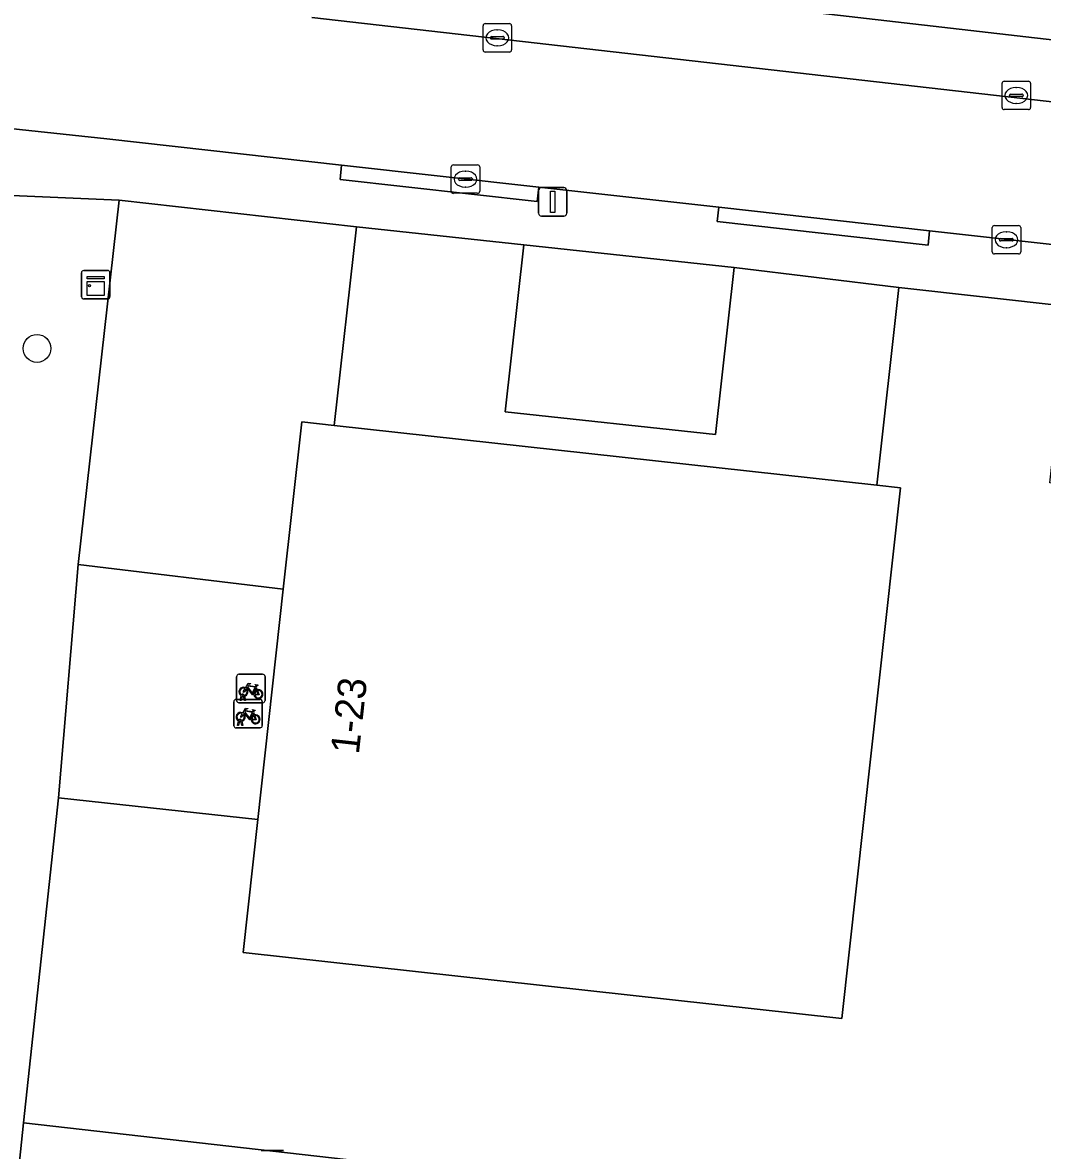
# Model space of a CAD drawing. Extents: x 161928 to 163071, y 386474 to 387428.
# Drawn here: x 162199.13 to 162234.98, y 387005.98 to 387045.64 of the extents above; entities that cross this region are included whole.
import ezdxf

# ---------------------------------------------------------------- set-up
doc = ezdxf.new("R2010")
doc.units = 0
for name, color, linetype in [('IMGEO_Boom', 7, 'Continuous'), ('IMGEO_Fietsenrek', 7, 'Continuous'), ('IMGEO_Groenvoorziening', 7, 'Continuous'), ('IMGEO_Kast', 7, 'Continuous'), ('IMGEO_Kolk', 7, 'Continuous'), ('IMGEO_Lichtmast', 7, 'Continuous'), ('IMGEO_Pand', 7, 'Continuous'), ('IMGEO_Pand_nummerreeks', 7, 'Continuous'), ('IMGEO_Parkeervlak_open', 7, 'Continuous'), ('IMGEO_Rijbaan_lokaal_open', 7, 'Continuous'), ('IMGEO_Voetpad_open', 7, 'Continuous')]:
    doc.layers.add(name, color=color, linetype=linetype)

msp = doc.modelspace()

# ---------------------------------------------------------------- linework, layer by layer
at = {"layer": 'IMGEO_Boom'}
msp.add_circle((162199.641, 387034.177), 0.489, dxfattribs=at)
at = {"layer": 'IMGEO_Fietsenrek'}
for p, q in [((162206.656, 387021.794), (162206.656, 387022.635)), ((162206.656, 387022.635), (162206.656, 387021.794)), ((162206.731, 387022.719), (162207.572, 387022.719)), ((162207.572, 387022.719), (162206.731, 387022.719)), ((162207.656, 387022.644), (162207.656, 387021.803)), ((162207.656, 387021.803), (162207.656, 387022.644)), ((162207.343, 387022.268), (162207.379, 387022.173)), ((162206.558, 387020.91), (162206.558, 387021.751)), ((162206.558, 387021.751), (162206.558, 387020.91)), ((162206.633, 387021.835), (162207.474, 387021.835)), ((162207.474, 387021.835), (162206.633, 387021.835)), ((162207.581, 387021.719), (162206.74, 387021.719)), ((162206.74, 387021.719), (162207.581, 387021.719)), ((162206.783, 387021.803), (162206.822, 387021.963)), ((162206.817, 387021.803), (162206.783, 387021.803)), ((162206.852, 387021.951), (162206.817, 387021.803)), ((162206.894, 387021.975), (162206.893, 387021.979)), ((162206.935, 387021.803), (162206.901, 387021.945)), ((162206.925, 387021.986), (162206.926, 387021.979)), ((162206.933, 387021.949), (162206.968, 387021.803)), ((162206.968, 387021.803), (162206.935, 387021.803)), ((162207.558, 387021.76), (162207.558, 387020.919)), ((162207.558, 387020.919), (162207.558, 387021.76)), ((162207.245, 387021.384), (162207.281, 387021.289)), ((162206.685, 387020.919), (162206.724, 387021.079)), ((162206.719, 387020.919), (162206.685, 387020.919)), ((162206.754, 387021.067), (162206.719, 387020.919)), ((162206.796, 387021.091), (162206.795, 387021.095)), ((162206.837, 387020.919), (162206.803, 387021.061)), ((162206.827, 387021.102), (162206.828, 387021.095)), ((162206.835, 387021.065), (162206.87, 387020.919)), ((162206.87, 387020.919), (162206.837, 387020.919)), ((162207.483, 387020.835), (162206.642, 387020.835)), ((162206.642, 387020.835), (162207.483, 387020.835))]:
    msp.add_line(p, q, dxfattribs=at)
for points in [[(162206.99, 387022.193), (162206.938, 387022.103), (162206.898, 387022.078), (162206.899, 387022.125), (162206.954, 387022.219)], [(162206.969, 387022.245), (162207.064, 387022.409), (162207.15, 387022.395), (162207.152, 387022.386), (162207.096, 387022.375), (162207.069, 387022.33), (162207.325, 387022.289)], [(162207.265, 387022.001), (162207.215, 387022.001), (162207.024, 387022.252), (162207.005, 387022.22)], [(162207.312, 387022.264), (162207.055, 387022.305), (162207.038, 387022.276), (162207.205, 387022.056), (162207.312, 387022.264)], [(162207.36, 387022.166), (162207.33, 387022.243), (162207.221, 387022.025), (162207.264, 387022.025)], [(162207.294, 387022.025), (162207.414, 387022.024), (162207.37, 387022.138)], [(162207.39, 387022.145), (162207.445, 387022), (162207.295, 387022)], [(162207.325, 387022.289), (162207.35, 387022.338), (162207.344, 387022.342), (162207.321, 387022.346), (162207.309, 387022.353), (162207.308, 387022.356), (162207.31, 387022.361), (162207.405, 387022.346), (162207.407, 387022.336), (162207.397, 387022.323), (162207.385, 387022.317), (162207.371, 387022.323), (162207.343, 387022.268)], [(162206.892, 387021.309), (162206.84, 387021.219), (162206.8, 387021.194), (162206.801, 387021.241), (162206.856, 387021.335)], [(162206.871, 387021.361), (162206.966, 387021.525), (162207.052, 387021.511), (162207.054, 387021.502), (162206.998, 387021.491), (162206.971, 387021.446), (162207.227, 387021.405)], [(162207.167, 387021.117), (162207.117, 387021.117), (162206.926, 387021.368), (162206.907, 387021.336)], [(162207.214, 387021.38), (162206.957, 387021.421), (162206.94, 387021.392), (162207.107, 387021.172), (162207.214, 387021.38)], [(162207.262, 387021.282), (162207.232, 387021.359), (162207.123, 387021.141), (162207.166, 387021.141)], [(162207.196, 387021.141), (162207.316, 387021.14), (162207.272, 387021.254)], [(162207.292, 387021.261), (162207.347, 387021.116), (162207.197, 387021.116)], [(162207.227, 387021.405), (162207.252, 387021.454), (162207.246, 387021.458), (162207.223, 387021.462), (162207.211, 387021.469), (162207.21, 387021.472), (162207.212, 387021.477), (162207.307, 387021.462), (162207.309, 387021.452), (162207.299, 387021.439), (162207.287, 387021.433), (162207.273, 387021.439), (162207.245, 387021.384)]]:
    msp.add_lwpolyline(points, dxfattribs=at)
for centre, radius, start, end in [((162206.734, 387022.641), 0.0779, 92.4484, 184.2845), ((162206.734, 387022.641), 0.0779, 92.4484, 184.2845), ((162207.578, 387022.641), 0.0779, 2.4484, 94.2845), ((162207.578, 387022.641), 0.0779, 2.4484, 94.2845), ((162206.896, 387022.104), 0.159, 62.6766, 242.1369), ((162206.896, 387022.104), 0.129, 63.3192, 238.903), ((162206.896, 387022.104), 0.129, 283.6043, 43.4302), ((162206.896, 387022.104), 0.159, 283.5766, 46.6042), ((162207.423, 387022.02), 0.159, 113.3408, 178.3217), ((162207.423, 387022.02), 0.159, 187.0065, 105.7708), ((162207.423, 387022.02), 0.129, 113.923, 177.9556), ((162207.423, 387022.02), 0.129, 188.6715, 104.5883), ((162206.636, 387021.757), 0.0779, 92.4484, 184.2845), ((162206.636, 387021.757), 0.0779, 92.4484, 184.2845), ((162206.734, 387021.797), 0.0779, 182.4484, 274.2845), ((162206.734, 387021.797), 0.0779, 182.4484, 274.2845), ((162206.876, 387021.975), 0.0499, 12.8025, 158.6934), ((162206.896, 387022.104), 0.159, 253.9967, 271.7867), ((162206.876, 387021.975), 0.0174, 12.8025, 163.4502), ((162206.896, 387022.104), 0.129, 253.415, 269.0204), ((162207.48, 387021.757), 0.0779, 2.4484, 94.2845), ((162207.48, 387021.757), 0.0779, 2.4484, 94.2845), ((162207.578, 387021.797), 0.0779, 272.4484, 4.2845), ((162207.578, 387021.797), 0.0779, 272.4484, 4.2845), ((162206.798, 387021.22), 0.159, 62.6766, 242.1369), ((162206.798, 387021.22), 0.129, 63.3192, 238.903), ((162206.798, 387021.22), 0.129, 283.6043, 43.4302), ((162206.798, 387021.22), 0.159, 283.5766, 46.6042), ((162207.325, 387021.136), 0.159, 113.3408, 178.3217), ((162207.325, 387021.136), 0.159, 187.0065, 105.7708), ((162207.325, 387021.136), 0.129, 113.923, 177.9556), ((162207.325, 387021.136), 0.129, 188.6715, 104.5883), ((162206.636, 387020.913), 0.0779, 182.4484, 274.2845), ((162206.636, 387020.913), 0.0779, 182.4484, 274.2845), ((162206.778, 387021.091), 0.0499, 12.8025, 158.6934), ((162206.798, 387021.22), 0.159, 253.9967, 271.7867), ((162206.778, 387021.091), 0.0174, 12.8025, 163.4502), ((162206.798, 387021.22), 0.129, 253.415, 269.0204), ((162207.48, 387020.913), 0.0779, 272.4484, 4.2845), ((162207.48, 387020.913), 0.0779, 272.4484, 4.2845)]:
    msp.add_arc(centre, radius, start, end, dxfattribs=at)
at = {"layer": 'IMGEO_Groenvoorziening'}
for points in [[(162202.53, 387039.39), (162201.091, 387026.577), (162208.295, 387025.714), (162208.944, 387031.594), (162210.08, 387031.469), (162210.868, 387038.451)], [(162224.147, 387037.026), (162216.749, 387037.817), (162216.094, 387031.943), (162223.491, 387031.152)], [(162235.923, 387035.657), (162229.928, 387036.317), (162229.156, 387029.365), (162229.989, 387029.273), (162227.931, 387010.613), (162206.885, 387012.934), (162207.401, 387017.613), (162200.393, 387018.378), (162199.167, 387006.944), (162231.748, 387003.246), (162249.668, 387001.212), (162250.432, 387008.128), (162246.936, 387008.514), (162240.704, 387009.203), (162241.052, 387012.44), (162241.4, 387015.676), (162241.748, 387018.913), (162242.095, 387022.149), (162242.443, 387025.386), (162242.791, 387028.622), (162235.238, 387029.457)]]:
    msp.add_lwpolyline(points, close=True, dxfattribs=at)
at = {"layer": 'IMGEO_Kast'}
for p, q in [((162201.206, 387035.994), (162201.206, 387036.835)), ((162201.206, 387036.835), (162201.206, 387035.994)), ((162201.281, 387036.919), (162202.122, 387036.919)), ((162202.122, 387036.919), (162201.281, 387036.919)), ((162202.206, 387036.844), (162202.206, 387036.003)), ((162202.206, 387036.003), (162202.206, 387036.844)), ((162202.131, 387035.919), (162201.29, 387035.919)), ((162201.29, 387035.919), (162202.131, 387035.919))]:
    msp.add_line(p, q, dxfattribs=at)
for points in [[(162201.401, 387036.709), (162202.001, 387036.709), (162202.001, 387036.624), (162201.401, 387036.624), (162201.401, 387036.709)], [(162201.401, 387036.534), (162202.001, 387036.534), (162202.001, 387036.045), (162201.401, 387036.045), (162201.401, 387036.534)]]:
    msp.add_lwpolyline(points, dxfattribs=at)
msp.add_circle((162201.485, 387036.383), 0.0377, dxfattribs=at)
for centre, start, end in [((162201.284, 387036.841), 92.4484, 184.2845), ((162201.284, 387036.841), 92.4484, 184.2845), ((162202.128, 387036.841), 2.4484, 94.2845), ((162202.128, 387036.841), 2.4484, 94.2845), ((162201.284, 387035.997), 182.4484, 274.2845), ((162201.284, 387035.997), 182.4484, 274.2845), ((162202.128, 387035.997), 272.4484, 4.2845), ((162202.128, 387035.997), 272.4484, 4.2845)]:
    msp.add_arc(centre, 0.0779, start, end, dxfattribs=at)
at = {"layer": 'IMGEO_Kolk'}
for p, q in [((162215.319, 387044.675), (162215.319, 387045.527)), ((162215.394, 387045.601), (162216.246, 387045.601)), ((162216.32, 387045.527), (162216.32, 387044.675)), ((162215.578, 387045.095), (162215.578, 387045.107)), ((162216.016, 387045.058), (162215.618, 387045.058)), ((162215.621, 387045.144), (162216.019, 387045.144)), ((162215.807, 387045.381), (162215.832, 387045.381)), ((162216.062, 387045.107), (162216.062, 387045.095)), ((162215.83, 387044.821), (162215.805, 387044.821)), ((162216.246, 387044.601), (162215.394, 387044.601)), ((162233.561, 387042.649), (162233.561, 387043.501)), ((162233.636, 387043.575), (162234.488, 387043.575)), ((162234.562, 387043.501), (162234.562, 387042.649)), ((162233.82, 387043.069), (162233.82, 387043.081)), ((162233.863, 387043.118), (162234.261, 387043.118)), ((162234.049, 387043.355), (162234.074, 387043.355)), ((162234.304, 387043.081), (162234.304, 387043.069)), ((162234.258, 387043.032), (162233.86, 387043.032)), ((162234.072, 387042.795), (162234.047, 387042.795)), ((162234.488, 387042.575), (162233.636, 387042.575)), ((162214.2, 387039.706), (162214.2, 387040.558)), ((162214.275, 387040.632), (162215.127, 387040.632)), ((162214.688, 387040.412), (162214.713, 387040.412)), ((162215.201, 387040.558), (162215.201, 387039.706)), ((162214.459, 387040.126), (162214.459, 387040.138)), ((162214.897, 387040.089), (162214.499, 387040.089)), ((162214.502, 387040.175), (162214.9, 387040.175)), ((162214.943, 387040.138), (162214.943, 387040.126)), ((162215.127, 387039.632), (162214.275, 387039.632)), ((162214.711, 387039.852), (162214.686, 387039.852)), ((162233.215, 387037.574), (162233.215, 387038.426)), ((162233.29, 387038.5), (162234.142, 387038.5)), ((162234.216, 387038.426), (162234.216, 387037.574)), ((162233.474, 387037.994), (162233.474, 387038.006)), ((162233.912, 387037.957), (162233.514, 387037.957)), ((162233.517, 387038.043), (162233.915, 387038.043)), ((162233.703, 387038.28), (162233.728, 387038.28)), ((162233.958, 387038.006), (162233.958, 387037.994)), ((162233.726, 387037.72), (162233.701, 387037.72)), ((162234.142, 387037.5), (162233.29, 387037.5))]:
    msp.add_line(p, q, dxfattribs=at)
for points in [[(162215.319, 387044.675), (162215.319, 387045.527)], [(162215.394, 387045.601), (162216.246, 387045.601)], [(162216.32, 387045.527), (162216.32, 387044.675)], [(162216.246, 387044.601), (162215.394, 387044.601)], [(162233.561, 387042.649), (162233.561, 387043.501)], [(162233.636, 387043.575), (162234.488, 387043.575)], [(162234.562, 387043.501), (162234.562, 387042.649)], [(162234.488, 387042.575), (162233.636, 387042.575)], [(162214.2, 387039.706), (162214.2, 387040.558)], [(162214.275, 387040.632), (162215.127, 387040.632)], [(162215.201, 387040.558), (162215.201, 387039.706)], [(162215.127, 387039.632), (162214.275, 387039.632)], [(162233.215, 387037.574), (162233.215, 387038.426)], [(162233.29, 387038.5), (162234.142, 387038.5)], [(162234.216, 387038.426), (162234.216, 387037.574)], [(162234.142, 387037.5), (162233.29, 387037.5)]]:
    msp.add_lwpolyline(points, dxfattribs=at)
for centre, radius, start, end in [((162215.396, 387045.525), 0.0765, 91.552, 178.448), ((162215.396, 387045.525), 0.0765, 91.552, 178.448), ((162216.244, 387045.525), 0.0765, 1.552, 88.448), ((162216.244, 387045.525), 0.0765, 1.552, 88.448), ((162215.618, 387045.104), 0.0403, 85.8775, 175.7526), ((162215.615, 387045.094), 0.0366, 178.938, 274.7102), ((162216.019, 387045.101), 0.043, 264.8664, 352.4533), ((162216.023, 387045.106), 0.0386, 1.7309, 96.639), ((162215.396, 387044.677), 0.0765, 181.552, 268.448), ((162215.396, 387044.677), 0.0765, 181.552, 268.448), ((162216.244, 387044.677), 0.0765, 271.552, 358.448), ((162216.244, 387044.677), 0.0765, 271.552, 358.448), ((162233.638, 387043.499), 0.0765, 91.552, 178.448), ((162233.638, 387043.499), 0.0765, 91.552, 178.448), ((162234.486, 387043.499), 0.0765, 1.552, 88.448), ((162234.486, 387043.499), 0.0765, 1.552, 88.448), ((162233.86, 387043.078), 0.0403, 85.8775, 175.7526), ((162233.857, 387043.068), 0.0366, 178.938, 274.7102), ((162234.261, 387043.075), 0.043, 264.8664, 352.4533), ((162234.265, 387043.08), 0.0386, 1.7309, 96.639), ((162233.638, 387042.651), 0.0765, 181.552, 268.448), ((162233.638, 387042.651), 0.0765, 181.552, 268.448), ((162234.486, 387042.651), 0.0765, 271.552, 358.448), ((162234.486, 387042.651), 0.0765, 271.552, 358.448), ((162214.277, 387040.556), 0.0765, 91.552, 178.448), ((162214.277, 387040.556), 0.0765, 91.552, 178.448), ((162215.125, 387040.556), 0.0765, 1.552, 88.448), ((162215.125, 387040.556), 0.0765, 1.552, 88.448), ((162214.499, 387040.135), 0.0403, 85.8775, 175.7526), ((162214.496, 387040.125), 0.0366, 178.938, 274.7102), ((162214.9, 387040.132), 0.043, 264.8664, 352.4533), ((162214.904, 387040.137), 0.0386, 1.7309, 96.639), ((162214.277, 387039.708), 0.0765, 181.552, 268.448), ((162214.277, 387039.708), 0.0765, 181.552, 268.448), ((162215.125, 387039.708), 0.0765, 271.552, 358.448), ((162215.125, 387039.708), 0.0765, 271.552, 358.448), ((162233.292, 387038.424), 0.0765, 91.552, 178.448), ((162233.292, 387038.424), 0.0765, 91.552, 178.448), ((162234.14, 387038.424), 0.0765, 1.552, 88.448), ((162234.14, 387038.424), 0.0765, 1.552, 88.448), ((162233.514, 387038.003), 0.0403, 85.8775, 175.7526), ((162233.511, 387037.993), 0.0366, 178.938, 274.7102), ((162233.915, 387038), 0.043, 264.8664, 352.4533), ((162233.919, 387038.005), 0.0386, 1.7309, 96.639), ((162233.292, 387037.576), 0.0765, 181.552, 268.448), ((162233.292, 387037.576), 0.0765, 181.552, 268.448), ((162234.14, 387037.576), 0.0765, 271.552, 358.448), ((162234.14, 387037.576), 0.0765, 271.552, 358.448)]:
    msp.add_arc(centre, radius, start, end, dxfattribs=at)
for centre, major_axis, ratio, start_param, end_param in [((162215.806, 387045.101), (-0.387, 0.002), 0.722429, 4.712389, 7.853982), ((162215.831, 387045.101), (-0.39, 0.002), 0.717154, 1.570796, 4.712389), ((162234.048, 387043.075), (-0.387, 0.002), 0.722429, 4.712389, 7.853982), ((162234.073, 387043.075), (-0.39, 0.002), 0.717154, 1.570796, 4.712389), ((162214.687, 387040.132), (-0.387, 0.002), 0.722429, 4.712389, 7.853982), ((162214.712, 387040.132), (-0.39, 0.002), 0.717154, 1.570796, 4.712389), ((162233.702, 387038), (-0.387, 0.002), 0.722429, 4.712389, 7.853982), ((162233.727, 387038), (-0.39, 0.002), 0.717154, 1.570796, 4.712389)]:
    msp.add_ellipse(centre, major_axis=major_axis, ratio=ratio, start_param=start_param, end_param=end_param, dxfattribs=at)
at = {"layer": 'IMGEO_Lichtmast'}
for p, q in [((162217.268, 387038.932), (162217.268, 387039.732)), ((162217.268, 387039.732), (162217.268, 387038.932)), ((162217.368, 387039.832), (162218.158, 387039.832)), ((162218.158, 387039.832), (162217.368, 387039.832)), ((162218.258, 387039.732), (162218.258, 387038.932)), ((162218.258, 387038.932), (162218.258, 387039.732)), ((162218.158, 387038.832), (162217.368, 387038.832)), ((162217.368, 387038.832), (162218.158, 387038.832)), ((162207.514, 387005.976), (162208.304, 387005.976)), ((162208.304, 387005.976), (162207.514, 387005.976))]:
    msp.add_line(p, q, dxfattribs=at)
msp.add_lwpolyline([(162217.688, 387039.707), (162217.838, 387039.707), (162217.838, 387038.957), (162217.688, 387038.957), (162217.688, 387039.707)], dxfattribs=at)
for centre, start, end in [((162217.368, 387039.732), 90, 180), ((162217.368, 387039.732), 90, 180), ((162218.158, 387039.732), 0, 90), ((162218.158, 387039.732), 360, 90), ((162217.368, 387038.932), 180, 270), ((162217.368, 387038.932), 180, 270), ((162218.158, 387038.932), 270, 0), ((162218.158, 387038.932), 270, 0)]:
    msp.add_arc(centre, 0.1, start, end, dxfattribs=at)
at = {"layer": 'IMGEO_Pand'}
msp.add_lwpolyline([(162208.944, 387031.594), (162208.295, 387025.714), (162207.401, 387017.613), (162206.885, 387012.934), (162227.931, 387010.613), (162229.989, 387029.273), (162229.156, 387029.365), (162210.08, 387031.469)], close=True, dxfattribs=at)
at = {"layer": 'IMGEO_Parkeervlak_open'}
for points in [[(162289.168, 387038.822), (162288.165, 387038.944), (162213.325, 387047.577)], [(162209.297, 387045.816), (162292.807, 387036.295)]]:
    msp.add_lwpolyline(points, dxfattribs=at)
at = {"layer": 'IMGEO_Rijbaan_lokaal_open'}
for points in [[(162293.928, 387036.193), (162292.807, 387036.295), (162209.297, 387045.816)], [(162184.213, 387043.306), (162187.102, 387043.012), (162194.737, 387042.328), (162202.099, 387041.543), (162210.343, 387040.623), (162217.274, 387039.85), (162223.604, 387039.144), (162231.014, 387038.317), (162250.997, 387036.088), (162256.711, 387035.451), (162290.902, 387031.456), (162293.855, 387031.139)]]:
    msp.add_lwpolyline(points, dxfattribs=at)
at = {"layer": 'IMGEO_Voetpad_open'}
for points in [[(162213.325, 387047.577), (162288.165, 387038.944), (162289.168, 387038.822)], [(162202.099, 387041.543), (162194.737, 387042.328), (162194.627, 387042.32), (162194.518, 387042.302), (162194.412, 387042.275), (162194.308, 387042.238), (162194.208, 387042.192), (162194.112, 387042.137), (162194.022, 387042.074), (162193.937, 387042.003), (162193.86, 387041.925), (162193.789, 387041.841), (162193.727, 387041.75), (162193.673, 387041.654), (162193.627, 387041.554), (162193.591, 387041.45), (162193.564, 387041.343), (162193.547, 387041.235), (162193.486, 387040.698), (162193.454, 387040.407)], [(162293.551, 387027.906), (162293.855, 387031.139), (162290.902, 387031.456), (162256.711, 387035.451), (162256.658, 387034.963), (162250.943, 387035.595), (162250.997, 387036.088), (162231.014, 387038.317), (162230.961, 387037.807), (162223.551, 387038.637), (162223.604, 387039.144), (162217.274, 387039.85), (162217.222, 387039.346), (162210.292, 387040.122), (162210.343, 387040.623), (162202.099, 387041.543)], [(162193.838, 387039.967), (162197.397, 387039.614), (162202.53, 387039.39), (162210.868, 387038.451), (162216.749, 387037.817), (162224.147, 387037.026), (162229.928, 387036.317), (162235.923, 387035.657), (162249.69, 387034.141), (162251.186, 387033.976), (162256.179, 387033.419), (162291.581, 387029.555)], [(162202.53, 387039.39), (162197.397, 387039.614)], [(162177.59, 387005.919), (162192.04, 387004.388), (162198.822, 387003.67), (162199.167, 387006.944), (162200.393, 387018.378), (162201.091, 387026.577), (162202.53, 387039.39)], [(162199.167, 387006.944), (162198.822, 387003.67), (162225.377, 387000.858), (162225.21, 386999.368), (162226.398, 386999.225)], [(162287.87, 386996.318), (162266.57, 386999.408), (162265.004, 386999.609), (162261.271, 387000), (162250.663, 387001.111), (162249.668, 387001.212), (162231.748, 387003.246), (162199.167, 387006.944)]]:
    msp.add_lwpolyline(points, dxfattribs=at)
for points in [[(162217.274, 387039.85), (162210.343, 387040.623), (162210.292, 387040.122), (162217.222, 387039.346)], [(162231.014, 387038.317), (162223.604, 387039.144), (162223.551, 387038.637), (162230.961, 387037.807)], [(162223.491, 387031.152), (162216.094, 387031.943), (162216.749, 387037.817), (162210.868, 387038.451), (162210.08, 387031.469), (162229.156, 387029.365), (162229.928, 387036.317), (162224.147, 387037.026)], [(162200.393, 387018.378), (162207.401, 387017.613), (162208.295, 387025.714), (162201.091, 387026.577)]]:
    msp.add_lwpolyline(points, close=True, dxfattribs=at)

# ---------------------------------------------------------------- texts
at = {"layer": 'IMGEO_Pand_nummerreeks'}
msp.add_text('1-23', height=1, rotation=83.7033, dxfattribs=at).set_placement((162210.952, 387019.883))

doc.saveas('drawing.dxf')
